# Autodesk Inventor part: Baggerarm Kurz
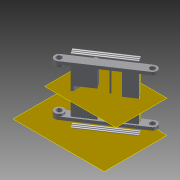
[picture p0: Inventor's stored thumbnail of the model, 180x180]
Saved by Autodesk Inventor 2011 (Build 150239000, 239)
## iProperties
Created: 2011-06
Part Number: Baggerarm Kurz
Document SubType Name: Modeling
Designer: Splendor
Density: 1 g/cm^3
Author: Splendor
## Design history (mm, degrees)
sketch "Skizze1"
  geometry: L1 (-166.594, 249.492)-(-3908.979, -2249.418); L2 (166.594, -249.492)-(-3575.791, -2748.402); C1 r 175 at (0, 0); C2 r 175 at (-3742.385, -2498.91); A1 r 300 centre (0, 0) between (166.594, -249.492) and (-166.594, 249.492); A2 r 300 centre (-3742.385, -2498.91) between (-3908.979, -2249.418) and (-3575.791, -2748.402); 1 further point
  constraints: 4 centre point, 4 end point, 4 point on circle, 4 tangent, 3 coincident, 1 parallel
  dimensions: "d0" = 600 distance between parallel lines of L1 L2; "d1" = 4500 distance of A2.centre point (0, 0); "d2" = 350 diameter of C1; "d3" = 350 diameter of C2
extrude "Extrusion1" new body sketch "Skizze1" distance "d4" = 200; taper "d5" = 0 deg
sketch "Skizze2"
  geometry: L1 (166.594, -249.492)-(-3575.791, -2748.402) reference; L2 (-3908.979, -2249.418)-(-166.594, 249.492) reference; L3 (-1071.697, -956.094)-(-387.922, -499.516); L4 (-387.922, -499.516)-(-610.047, -166.86); L5 (-610.047, -166.86)-(-1293.822, -623.438); L6 (-1293.822, -623.438)-(-1071.697, -956.094); L7 (-2069.666, -1622.47)-(-3132.338, -2332.05); L8 (-3132.338, -2332.05)-(-3354.463, -1999.394); L9 (-3354.463, -1999.394)-(-2291.791, -1289.814); L10 (-2291.791, -1289.814)-(-2069.666, -1622.47); C1 r 175 at (-3742.385, -2498.91) reference; C2 r 175 at (0, 0) reference; C3 r 50 at (-1671.549, -1138.223)
  constraints: 16 end point, 5 parallel, 3 perpendicular, 1 centre point
  dimensions: "d6" = 100 diameter of C3; "d7" = 100 distance between parallel lines of L2 L9; "d8" = 100 distance between parallel lines of L2 L5; "d9" = 100 distance between parallel lines of L1 L3; "d10" = 100 distance between parallel lines of L1 L7; "d11" = 600 distance from line of C3.centre L10; "d12" = 600 distance from line of L6 C3.centre; "d13" = 600 distance from line of C2.centre L4; "d14" = 600 distance from line of L8 C1.centre
extrude "Extrusion2" join sketch "Skizze2" distance "d15" = 3000; taper "d16" = 0 deg
workplane "Arbeitsebene2"
mirror "Spiegeln2"
sketch "Skizze3"
  geometry: L1 (166.594, -249.492)-(-3575.791, -2748.402) reference; C1 r 175 at (-3742.385, -2498.91) reference; C2 r 300 at (-3742.385, -2498.91); C3 r 175 at (-3742.385, -2498.91); A1 r 300 centre (-3742.385, -2498.91) between (-3908.979, -2249.418) and (-3575.791, -2748.402) reference
  constraints: 2 centre point, 2 coincident, 1 concentric, 1 tangent
extrude "Extrusion3" join sketch "Skizze3" distance "d19" = 150; taper "d20" = 0 deg
sketch "Skizze4"
  geometry: C1 r 175 at (4500, 300) reference; C2 r 175 at (4500, 300); C3 r 300 at (4500, 300); A1 r 300 centre (4500, 300) between (4500, 0) and (4500, 600) reference
  constraints: 2 centre point, 2 coincident, 2 concentric
extrude "Extrusion4" join sketch "Skizze4" distance "d21" = 150; taper "d22" = 0 deg
sketch "Skizze5"
  geometry: L1 (1277.801, 3000)-(0, 3000) reference; L2 (1277.801, 0)-(0, 0) reference; L3 (1277.801, 0)-(1277.801, 3000) reference; L4 (1277.801, 1800)-(377.801, 1800); L5 (377.801, 1800)-(377.801, 1200); L6 (377.801, 1200)-(1277.801, 1200); L7 (1277.801, 1200)-(1277.801, 1800); 1 further point
  constraints: 8 end point, 2 parallel, 1 horizontal, 1 perpendicular, 1 point on line
  dimensions: "d23" = 1200 distance between parallel lines of L4 L1; "d24" = 1200 distance between parallel lines of L2 L6; "d25" = 900 distance between parallel lines of L3 L5
extrude "Extrusion5" cut sketch "Skizze5" stored distance "d26" = 10; taper "d27" = 0 deg
sketch "Skizze6"
  geometry: L1 (900, 0)-(900, 400) reference; L2 (900, 0)-(1134.841, 0); L3 (1134.841, 0)-(900, 400); L4 (900, 0)-(900, 400); 1 further point
  constraints: 6 end point, 1 collinear, 1 perpendicular
extrude "Extrusion6" cut sketch "Skizze6" stored distance "d28" = 10; taper "d29" = 0 deg
workplane "Arbeitsebene3"
workplane "Arbeitsebene5"
workplane "Arbeitsebene6"
sketch "Skizze10"
  geometry: L1 (-166.594, -249.492)-(3575.791, -2748.402) reference; L2 (3908.979, -2249.418)-(166.594, 249.492) reference; L3 (281.064, -659.548)-(832.705, 166.594); L4 (3544.125, -1715.354)-(2813.14, -2810.084); L5 (582.282, -208.442)-(3326.698, -2040.976); L6 (498.985, -333.188)-(3243.401, -2165.722); L7 (415.688, -457.934)-(3160.104, -2290.468); C1 r 175 at (3742.385, -2498.91) reference; C2 r 175 at (0, 0) reference; A1 r 300 centre (0, 0) between (166.594, 249.492) and (-166.594, -249.492) reference; A2 r 300 centre (3742.385, -2498.91) between (3575.791, -2748.402) and (3908.979, -2249.418) reference; 1 further point
  constraints: 10 end point, 6 point on line, 3 parallel, 2 perpendicular
  dimensions: "d49" = 600 distance of L6.start point (0, 0); "d53" = 600 distance from line of L4 C1.centre
sketch "Skizze11"
  geometry: C1 r 55 at (3650, 350); C2 r 55 at (3650, 200); C3 r 55 at (3650, 50); 4 further points
  constraints: 3 centre point, 3 coincident
  dimensions: "d54" = 110 diameter of C1; "d55" = 110 diameter of C2; "d56" = 110 diameter of C3
feature "Sweeping2" sketch "Skizze10", "Skizze11" dims "d57" = 0
mirror "Spiegeln4"
node "Volumenkörper1"
node "Projizierte Kontur2"
feature "䁼"
other parameters: "d35" = 0
